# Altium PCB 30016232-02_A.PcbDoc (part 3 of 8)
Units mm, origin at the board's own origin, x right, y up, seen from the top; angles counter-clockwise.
Board outline 210 x 130 mm, 8 copper layers (1-TOP, 2-GND, 3-INTOP, 4-PWR, 5-PWR, 6-INBOT, 7-GND, 8-BOTTOM), stack 1.646 mm thick; 754 components, 649 nets, 2976 pads, 2161 vias.
Unrouted connection lines stored in the file: 22.
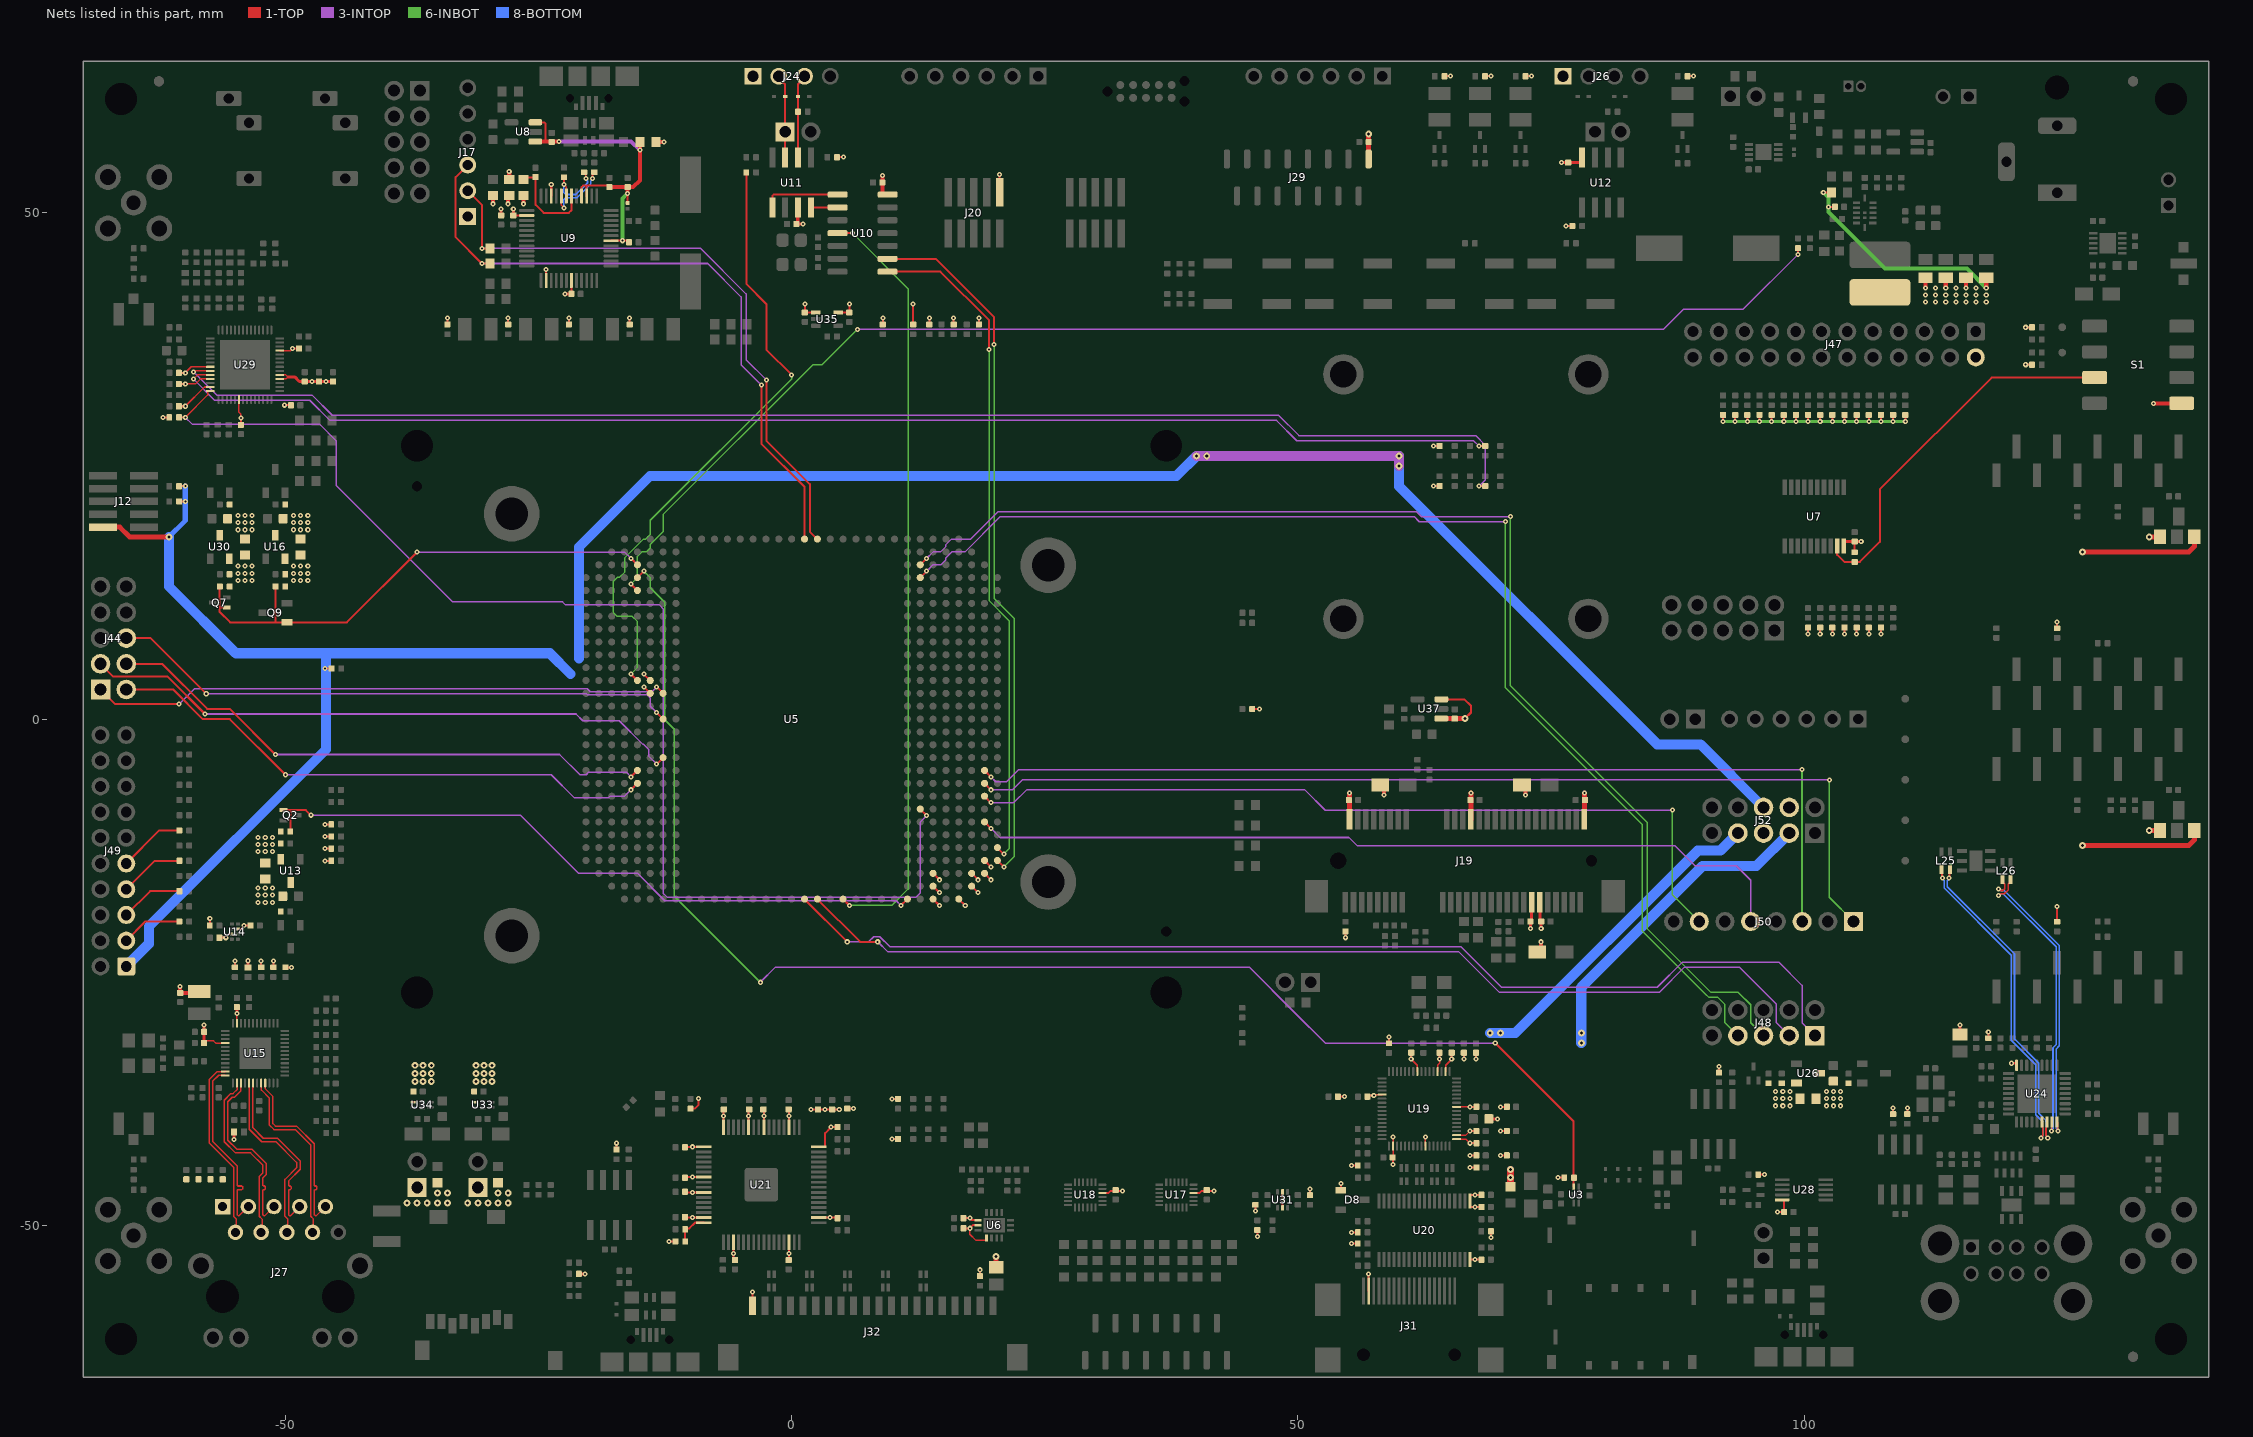
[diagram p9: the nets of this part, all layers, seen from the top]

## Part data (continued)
J3 J6 J7 J8 J9 J23 J25 J36: library part 1001128, "CONN HEADER 2POS .100\" SGL GOLD", Manufacturer=Samtec, Manufacturer_Part_Number=TSW-102-07-G-S, Package_Type=TH
J4: library part 1001136, "CONN HEADER 2POS 1.25MM VERT TIN", Manufacturer=Molex, Manufacturer_Part_Number=53047-0210, Package_Type=TH
J10 J13 J15: library part 1000027, "RF Connectors U.FL RECEPTACLE SMT GLD M CONTACT", Manufacturer=Hirose, Package_Type=SMT
J11 J14 J51: library part 1002720, "CONN SMA JACK R/A 50 OHM L15.1MM PCB TH", Manufacturer="Bobbintron Electrical Corp", Package_Type=TH
J12 J20 J22: library part 1000034, "CONN HEADER 10POS DUAL .05\" SMD", Manufacturer=Samtec, Package_Type=SMT
J16 J34 J35: library part 1001117, "CONN RECEPT MICRO-USB TYPE AB R/A", Manufacturer=KYCON, Package_Type=SMT
J17 J28 J43 J46: library part 1002721, "CONN HEADER VERT 6POS 2.54MM", Manufacturer=Molex, Package_Type=TH
J18: library part 1001118, "CONN TRANSFLSH R/A PUSH-PUSH SMD", Manufacturer=Molex, Package_Type=SMT
J19: library part 1001130, "SMCONN,MINI PCI EXP, 6.8MM HT", Manufacturer=Foxconn, Manufacturer_Part_Number=AS0B226-S68Q-7H, Package_Type=SMT
J21: library part 1001120, "MEMORY CARD 6POS PUSH/PULL SMD", Manufacturer=Molex, Package_Type=SMT
J24 J26: library part 1002743, "CONN HEADER VERT 4POS 2.54MM", Manufacturer=Semtech, Manufacturer_Part_Number=TSW-104-14-G-S, Package_Type=TH
J27: library part 1002612, "CONN MAGJACK 1PORT 1000 BASE-T IND", Manufacturer=XMultiple, Manufacturer_Part_Number=XMG-J1B2211NPA-1-DIG, Package_Type=TH
J29 J30: library part 1001866, "CONN FFC FPC VERT 15POS 1MM SMD", Manufacturer=FCI, Package_Type=SMT
J31: library part 1001123, "HDMI RECEPTACLE, SMT", Manufacturer=KYCON, Package_Type=SMT
J32: library part 1001132, "CONN HEADER 20POS 1.25MM R/A SMD", Manufacturer=Hirose, Manufacturer_Part_Number=DF14A-20P-1.25H, Package_Type=SMT
J33: library part 1001121, "USB Stacked Dual A type", Manufacturer=KYCON, Package_Type=TH
J37 J38: library part 1002596, "CONN JACK STEREO 3.5MM R/A", Manufacturer="CUI Inc.", Manufacturer_Part_Number=SJ1-3533NG, Package_Type=TH
J39 J40 J41 J42: library part 1001495, "CONN RCPT 2MM 10POS SMD", Manufacturer=Samtec, Package_Type=SMT
J44 J45 J48 J52 J53: library part 1001335, "CONN HEADER 10POS DL VERT T/H", Manufacturer=Molex, Manufacturer_Part_Number=87914-1016, Package_Type=TH
J47: library part 1002752, "CONN HEADER VERT 24POS 2.54MM", Manufacturer=Samtec, Package_Type=TH
J49: library part 1002751, "CONN HEADER VERT 20POS 2.54MM", Manufacturer=Samtec, Package_Type=TH
J50: library part 1000191, "CONN HEADER 8POS .100\" SNGL", Manufacturer=Samtec, Manufacturer_Part_Number=TSW-108-07-G-S, Package_Type=TH
L1: library part 1002747, "FIXED IND 4.7UH 4.5A 27.6 MOHM", Manufacturer=Murata, Manufacturer_Part_Number=1255AY-4R7M{}P3, Package_Type=SMT
L2 L4 L17 L18 L19 L22 L23 L24 L27 L29 L30 L31 L38 L39 L40 L41: library part 1001174, "FERRITE BEAD 220 OHM 2.0A 0805", Manufacturer="Wurth Electronics Inc", Manufacturer_Part_Number=742792022, Package_Type=0805
L3 L20 L21 L25 L26 L28: library part 1001173, "CHOKE COM MODE 120 OHM .37A", Manufacturer="Wurth Electronics Inc", Package_Type=SMT
L5: library part 1002610, "FIXED IND 4.7UH 1.1A 110 MOHM", Manufacturer=Samsung, Manufacturer_Part_Number=CIG22L4R7MNE, Package_Type=2520, Tolerance=20%
L6 L7: library part 1001175, "FERRITE BEAD 120 OHM .35A 0402", Manufacturer="Wurth Electronics Inc", Manufacturer_Part_Number=7427927112, Package_Type=0402
L8 L9 L10 L11 L12 L13 L14 L15 L16: library part 1001014, "CHOKE COIL COMMON MODE 150MA SMD", Manufacturer=Murata, Manufacturer_Part_Number=DLP11SN900HL2L, Package_Type=SMT
L32 L33 L34 L35 L36 L37: library part 1002041, "FERRITE BEAD 1.8 KOHM 0402 1LN", Manufacturer=Murata, Manufacturer_Part_Number=BLM15HD182SN1D, Package_Type=0402
Q1 Q2 Q4 Q6 Q7 Q11 Q12 Q13: library part 1000715, "MOSFET N-CH 60V 115MA SOT-523F", Manufacturer="Fairchild Semiconductor", Package_Type=SOT523F
Q3 Q5 Q8 Q9 Q10: library part 1000306, "MOSFET N-CH 30V 500MA SOT-23", Manufacturer="On Semiconductor", Package_Type=SOT23
R1 R231 R251 R254 R255 R256: library part 1001155, "RES 47.0K OHM 1/16W 1% 0402 SMD", Manufacturer="Vishay Dale", Manufacturer_Part_Number=CRCW040247K0FKED, Package_Type=0402, Tolerance=1%
R2 R4 R5 R6 R8 R22 R36 R37 R38 R39 R40 R41 R43 R44 R45 R47 R48 R49 R50 R51 R52 R54 R55 R56 R57 R58 R59 R60 R61 R62 R78 R125 R126 R127 R128 R129 R130 R131 R155 R156 R165 R167 R179 R224 R229 R232 R269 R270 R271 R272 R274 R275 R276 R277 R286 R287 R288 R289 R290 R293 R296 R297 R298 R299 R300 R301 R302 R303 R304 R305 R306 R308 R309 R310 R311 R313 R322 R323 R326 R328 R330 R331 R332 R333 R334 R335 R336 R340 R342 R343 R344 R345 R346 R347 R352 R353 R354 R359 R360: library part 1000076, "RES 0.0 OHM 1/10W 0402 SMD", Manufacturer="Panasonic - ECG", Manufacturer_Part_Number=ERJ-2GE0R00X, Package_Type=0402, Power=10
R3 R9 R11 R20 R21 R25 R80 R82 R84 R101 R102 R103 R104 R105 R106 R107 R108 R109 R110 R111 R112 R113 R114 R115 R116 R158 R174 R260 R281 R285 R317 R318 R319 R320 R321 R341 R348 R357: library part 1000480, "RES 100K OHM 1/10W 1% 0402 SMD", Manufacturer="Panasonic - ECG", Manufacturer_Part_Number=ERJ-2RKF1003X, Package_Type=0402, Power=100, Tolerance=1%
R7 R42 R46 R53 R117 R157 R159 R160 R164 R171 R173 R177 R181 R183 R184 R186 R187 R188 R189 R190 R191 R192 R193 R195 R196 R197 R198 R199 R200 R201 R202 R225 R243 R244 R247 R248 R250 R252 R258 R261 R262 R268 R279 R283 R307 R312 R337 R338 R350 R351: library part 1000537, "RES 10.0K OHM 1/10W 1% 0402 SMD", Manufacturer="Panasonic - ECG", Manufacturer_Part_Number=ERJ-2RKF1002X, Package_Type=0402, Power=100, Tolerance=1%
R10: library part 1001154, "RES 220 OHM 1/16W 1% 0402 SMD", Manufacturer=Yageo, Manufacturer_Part_Number=RC0402FR-07220RL, Package_Type=0402, Tolerance=1%
R12 R13 R18 R19 R28 R29 R30 R31 R32 R33 R34 R35 R63 R64 R65 R66 R67 R68 R132 R133 R134 R135 R136 R141 R142 R146 R147 R151 R152 R153 R154 R170 R203 R204 R205 R206 R207 R208 R209 R210 R211 R212 R213 R214 R215 R216 R217 R218 R219 R220 R221 R222 R223 R235 R236 R237 R238 R239 R240 R241 R257 R263 R265 R266 R267 R278 R282 R349 R355 R356: library part 1000208, "RES 0.0 OHM 1/10W 0603", Manufacturer="Panasonic - ECG", Manufacturer_Part_Number=ERJ-3GEY0R00V, Package_Type=0603, Voltage=75V
R14 R27 R137 R175 R253: library part 1001200, "RES 12.0K OHM 1/10W 1% 0603 SMD", Manufacturer=Yageo, Manufacturer_Part_Number=RC0603FR-0712KL, Package_Type=0603, Power=100, Tolerance=1
R15 R273 R291 R292 R294 R295 R327 R329: library part 1001156, "RES 2.20K OHM 1/16W 1% 0402 SMD", Manufacturer=Yageo, Manufacturer_Part_Number=RC0402FR-072K2L, Package_Type=0402, Tolerance=1%
R16: library part 1000711, "RES 10.0 OHM 1/10W 1% 0402 SMD", Manufacturer="Panasonic - ECG", Manufacturer_Part_Number=ERJ-2RKF10R0X, Package_Type=0402, Power=100, Tolerance=1%
R17 R140 R358: library part 1000142, "RES 20K OHM 1/10W 5% 0603 SMD", Manufacturer="Panasonic - ECG", Manufacturer_Part_Number=ERJ-3GEYJ203V, Package_Type=0603, Power=100, Tolerance=5
R23 R26: library part 1000701, "RES 470K OHM 1/10W 1% 0402 SMD", Manufacturer="Panasonic - ECG", Manufacturer_Part_Number=ERJ-2RKF4703X, Package_Type=0402, Power=100, Tolerance=1%
R24: library part 1001518, "RES 53.6K OHM 1/10W 1% 0603 SMD", Manufacturer="Panasonic - ECG", Manufacturer_Part_Number=ERJ-3EKF5362V, Package_Type=0603
R69 R70 R71 R72 R138 R139 R161 R324 R325: library part 1000601, "RES 22.0 OHM 1/10W 1% 0402 SMD", Manufacturer="Panasonic - ECG", Manufacturer_Part_Number=ERJ-2RKF22R0X, Package_Type=0402, Power=100, Tolerance=1%
R73 R74 R75 R76 R162 R163: library part 1000466, "RES 49.9 OHM 1/10W 1% 0402 SMD", Manufacturer="Panasonic - ECG", Manufacturer_Part_Number=ERJ-2RKF49R9X, Package_Type=0402, Power=100, Tolerance=1%
R77 R79 R81 R83 R85 R86 R87 R88 R89 R90 R91 R92 R93 R94 R95 R96 R97 R98 R99 R100 R118 R119 R120 R121 R122 R123 R124 R185 R233 R234 R242 R245 R246: library part 1000038, "RES 4.7K OHM 1/10W 5% 0402 SMD", Manufacturer="Panasonic - ECG", Manufacturer_Part_Number=ERJ-2GEJ472X, Package_Type=0402, Power=100, Tolerance=5
R143 R144 R148 R150 R166 R169 R172 R176 R182 R259 R280 R284 R314 R315 R316: library part 1001158, "RES 120 OHM 1/16W 1% 0402 SMD", Manufacturer=Yageo, Manufacturer_Part_Number=RC0402FR-07120RL, Package_Type=0402, Tolerance=1%
R145: library part 1001772, "SMRES, 1.5K OHM 0.063W 0402 1%", Manufacturer="Vishay Dale", Manufacturer_Part_Number=CRCW04021K50FKED, Package_Type=0402, Power=63, Tolerance=1%
R149: library part 1001000, "RES 470 OHM 1/20W 1% 0201 SMD", Manufacturer=KOA, Manufacturer_Alt_1="Panasonic - ECG", Manufacturer_Alt_1_Part_Number=ERJ-1GNF4700C, Manufacturer_Alt_2="Vishay Dale", Manufacturer_Alt_2_Part_Number=CRCW0201470RFKED, Manufacturer_Part_Number=RK73H1HTTC4700F, Package_Type=0201, Power=50, Tolerance=1
R168 R178 R264: library part 1000079, "RES 1.00K OHM 1/10W 1% 0402 SMD", Manufacturer="Panasonic - ECG", Manufacturer_Part_Number=ERJ-2RKF1001X, Package_Type=0402, Power=10
R180: library part 1000229, "RES 0.0 OHM 1/2W 1210 SMD", Manufacturer="Vishay Dale", Manufacturer_Part_Number=CRCW12100000Z0EA, Package_Type=1210
R194: library part 1000469, "RES 2.37K OHM 1/10W 1% 0402 SMD", Manufacturer="Panasonic - ECG", Manufacturer_Part_Number=ERJ-2RKF2371X, Package_Type=0402, Power=100, Tolerance=1%
R226: library part 1001153, "RES 27.0K OHM 1/16W 1% 0402 SMD", Manufacturer=Yageo, Manufacturer_Part_Number=RC0402FR-0727KL, Package_Type=0402, Tolerance=1%
R227 R249: library part 1000971, "RES 1.00M OHM 1/16W 1% 0402 SMD", Manufacturer=Yageo, Manufacturer_Part_Number=RC0402FR-071ML, Package_Type=0402, Power=63, Tolerance=1
R228: library part 1002748, "RES 5.97K OHM 0.1% 1/10W 0402", Manufacturer="Vishay Dale", Manufacturer_Part_Number=TNPW04025K97BEED, Package_Type=0402
R230: library part 1000174, "RES 15.0K OHM 1/10W 1% 0402 SMD", Manufacturer="Panasonic - ECG", Manufacturer_Part_Number=ERJ-2RKF1502X, Package_Type=0402, Power=10, Tolerance=1%
R339: library part 1000980, "RES 2.2M OHM 1/20W 5% 0201 SMD", Manufacturer=Rohm, Manufacturer_Alt_1="Panasonic - ECG", Manufacturer_Alt_1_Part_Number=ERJ-1GEJ225C, Manufacturer_Part_Number=MCR006YZPJ225, Package_Type=0201, Power=50, Tolerance=5
S1: library part 1002122, "SWITCH SLIDE DIP SPST 100MA 20V", Manufacturer=CTS, Package_Type=SOIC
SW1 SW2 SW3 SW4: library part 1001124, "SWITCH TACTILE SPST-NO 0.05A 32V", Manufacturer=ITT, Package_Type=SMT
SWD: library part CAD0066, "CBL PLUG-OF-NAILS 10-PIN", Package_Type=SMT
TP1 TP2 TP3 TP4 TP5 TP6 TP7: library part CAD0011, "TEST POINT 30MIL PAD SMT", Package_Type=TP
U1: library part 1002744, "IC ELECTRONIC FUSE 10VFDFPN", Manufacturer=STMicroelectronics, Package_Type=SON
U2 U8 U37: library part 1001979, "IC REG LDO ADJ 0.15A SOT25", Manufacturer="Diodes, Inc.", Manufacturer_Part_Number=AP2202K-ADJTRG1, Package_Type=SOT23-5
U3 U33 U34: library part 1001857, "IC SW W/CTRL SLEW RATE 4TDFN", Manufacturer="Vishay Siliconix", Manufacturer_Part_Number=SIP32401ADNP-T1GE4, Package_Type=SON
U4: library part 1001907, "IC REG BUCK ADJ 3A SYNC", Manufacturer="Linear Technology", Manufacturer_Part_Number=MP2316GD, Package_Type=QFN
U5: library part 1002739, "ConnectCore for i.MX8M Nano module - LGA", Manufacturer=DIGI, Manufacturer_Part_Number=50002014-01
U6: library part 1002449, "SMIC PCIE CLOCK GEN 100MHZ 14QFN", Manufacturer="Abracon Corporation", Package_Type=QFN
U7: library part 1001368, "IC SWITCH BUS 8BIT FET 20-TSSOP", Manufacturer="Texas Instruments", Package_Type=TSSOP
U9: library part 1002724, "IC USB FS DUAL UART/FIFO 48-LQFP", Manufacturer="FTDI Chip", Package_Type=QFP
U10: library part 1002729, "IC CANBUS CONTROLLER SPI 14SOIC", Manufacturer=Microchip, Manufacturer_Part_Number=MCP2517FD-H/SL, Package_Type=SOIC
U11: library part 1002681, "IC CAN TRANSEIVER HS 8SOIC", Manufacturer="Texas Instruments", Package_Type=SOIC
U12: library part 1001420, "IC TRANSCEIVER RS485 8-SOIC", Manufacturer="Linear Technology", Package_Type=SOIC
U13 U16 U26 U30: library part 1001163, "MOSFET P-CH 20V 3.7A SOT23-3", Manufacturer="Vishay Siliconix", Package_Type=SMT
U14: library part 1002597, "IC TRANSLATING TXRX 8XSON", Manufacturer="NXP Semiconductors", Manufacturer_Part_Number=NTS0102GT,115, Package_Type=PSON
U15: library part 1002583, "IC TRANSCEIVER ETHERNET 48-QFN", Manufacturer="Qualcomm Atheros, Inc.", Package_Type=QFN
U17 U18: library part 1002697, "IC SWITCH TPDT DIFF XQFN24", Manufacturer="NXP Semiconductors", Manufacturer_Part_Number=NX3DV642GU, Package_Type=QFN
U19: library part 1002722, "MIPI DSI BRIDGE TO LVDS/HDMI SINGLE CHANNEL", Manufacturer="Lontium Semiconductor", Package_Type=QFN
U20: library part 1001125, "IC HDMI XMITTER PORT P/I 38TSSOP", Manufacturer="On Semiconductor", Package_Type=SOP
U21: library part 1002718, "IC BRIDGE DSI TO LVDS 64HTQFP", Manufacturer="Texas Instruments", Package_Type=QFP
U22 U25: library part 1001265, "TVS DIODE 5.5VWM 6SON", Manufacturer="Texas Instruments", Package_Type=SMT
U23 U27 U36: library part 1001143, "IC SW DISTRIBUTION 2CHAN 8SOIC", Manufacturer=Micrel, Manufacturer_Part_Number=MIC2026-1YM, Package_Type=SOIC
U24: library part 1001114, "4-PORT USB 2.0 HUB CTRLR 36VQFN", Manufacturer=SMSC, Package_Type=QFN
U28: library part 1002730, "IC USB SWITCH DUAL 2X1 10MSOP", Manufacturer="On Semiconductor", Package_Type=SOP
U29: library part 1002001, "IC CODEC AUDIO FLEXSOUND 56TQFN", Manufacturer=Maxim, Manufacturer_Part_Number=MAX98089ETN+T, Package_Type=QFN
U31: library part 1001009, "MOSFET DL N-CH 60V 410MA SOT-563", Manufacturer="Diodes, Inc.", Package_Type=SOT523F
U32: library part 1000217, "IC OPAMP DUAL 1.6V 9KHZ 8TDFN", Manufacturer=Microchip, Package_Type=DFN
U35: library part 1000759, "TRANSLATOR 1BIT UNIDIRECT SC70-", Manufacturer="Fairchild Semiconductor", Package_Type=SC70
X1: library part 1002725, "Crystals 6MHz lo-profile", Manufacturer="Vishay Semiconductors", Manufacturer_Part_Number=XT9M20HRR6M, Package_Type=SMT
X2: library part 1002203, "CRYSTAL 40.0000MHz 9pF -40°C - 85°C DFN LCC", Manufacturer=Raltron, Package_Type=OSCCC
X3 X4: library part 1001497, "SMCRY,25MHZ 50PPM 20PF RH100 EXT", Manufacturer=Raltron, Package_Type=SMT
X5: library part 1001134, "CRYSTAL 24MHZ 18PF SMD", Manufacturer=Aker, Manufacturer_Part_Number=C3E-24.000-18-3030-X-R, Package_Type=SMT

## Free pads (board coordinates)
  round 5.5 / inner round 0 / far side round 5.5 hole 3.2: 0(-27.65,-21.4) 0(-27.65,20.275) 0(25.35,-16.1) 0(25.35,15.2)
  round 4 / inner round 0 / far side round 5.5 hole 2.6: 0(54.5,34.05) 0(78.7,34.05) C(54.5,9.9) C(78.7,9.9)

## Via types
v1: diameter 0.5, hole 0.2, 1-TOP to 8-BOTTOM, 1742 vias
v2: diameter 0.5/0.5/0.5/0.5 (per signal layer), hole 0.2, 1-TOP to 8-BOTTOM, 237 vias
v3: diameter 0.68, hole 0.3, 1-TOP to 8-BOTTOM, 182 vias

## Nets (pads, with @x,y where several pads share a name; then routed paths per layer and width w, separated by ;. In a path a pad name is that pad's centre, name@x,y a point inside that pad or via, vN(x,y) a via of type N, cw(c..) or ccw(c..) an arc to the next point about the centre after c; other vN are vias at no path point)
1V8: C190.2 R37.1 R77.2 R79.2 R81.1 R83.1 R323.1 R345.1 R347.1 U5.AH1 U5.AH2 U5.AH3 U34.3 | length 7.7
  1-TOP w0.2: v1(-46.12,-14) R347.1@-45.48,-14 ; v1(-46.1,-12.8) R345.1@-45.48,-12.8 ; v1(-46.1,-11.6) R37.1@-45.48,-11.6 ; R323.1@9,38.98 v1(9,39.6) ; U5.AH1@13.97,-17.78 v1(14.605,-18.415) ; U5.AH2@13.97,-16.51 v1(14.605,-17.145) ; U5.AH3@13.97,-15.24 v1(14.605,-15.875) ; R81.1@15.99,39 v1(15.99,39.62) ; R83.1@18.5,38.98 v1(18.5,39.62) ; v1(121.9,35) R79.2@122.52,35 ; v1(121.9,38.7) R77.2@122.52,38.7
  other v3: -37.2,-35.8 -36.4,-35.8 -35.6,-35.8 -37.2,-35 -36.4,-35 -35.6,-35 -37.2,-34.2 -36.4,-34.2 -35.6,-34.2
1V8_CODEC: C162.2 C164.2 C165.1 C166.1 C167.1 R282.2 R284.1 U16.D U29.25 U29.50 U29.53 | length 9.3
  1-TOP w0.15: v1(-59.9,33.1) -58.9,33.1 -58.4,33.6 U29.53@-57.43,33.6 ; v1(-59.9,34.2) -59.3,34.8 U29.50@-57.43,34.8 ; U29.25@-50.57,36.4 -49.5,36.4 v1(-49.3,36.6)
  1-TOP w0.2: C166.1@-60.54,33.1 v1(-59.9,33.1) ; C165.1@-60.54,34.2 v1(-59.9,34.2) ; v1(-50.1,31) C164.2@-49.46,31 ; v1(-49.3,36.6) C167.1@-48.66,36.6
  other v1: -49.2,18.7 -48.5,18.7 -47.8,18.7 -49.2,19.4 -48.5,19.4 -47.8,19.4 -49.2,20.1 -48.5,20.1 -47.8,20.1
1V8_SOM_EXT: C60.2 C87.2 C88.2 C89.2 C90.2 C91.2 C94.2 C95.2 C97.2 C98.2 C99.2 C100.2 C102.2 C103.2 C104.2 C105.2 C106.2 C107.2 C108.2 C109.2 C112.2 C113.2 C114.2 C115.2 C116.2 C117.2 C118.2 C119.2 C120.2 C121.2 C122.2 C123.2 C197.2 J8.1 J20.1 J52.7 R32.2 R164.1 R173.1 R183.2 R224.2 R225.1 R231.1 R245.2 R282.1 R283.1 R285.1 R294.2 R295.2 R327.2 R329.2 U14.3 U16.S U19.5 U19.18 U19.26 U19.33 U19.34 U19.41 U19.50 U19.52 U19.57 U21.3 U21.14 U21.18 U21.32 U21.35 U21.40 U21.43 U21.48 U21.49 U21.55 U21.58 U21.63 U31.2 U31.5 U35.5 | length 96.3
  1-TOP w0.15: v1@57.5,-37.1 U19.5@58.32,-37.1 ; C89.2@59.4,-43.3 U19.18@59.4,-42.18 v1(59.4,-41.3) ; v1(61.2,-33.6) 61.8,-34.2 U19.57@61.8,-34.82 ; U19.26@62.6,-42.18 v1(62.6,-41.3) ; U19.52@63.8,-34.82 63.8,-34.2 64,-34 v1(64,-33.6) ; U19.50@64.6,-34.82 64.6,-34.2 v1(65.2,-33.6) ; U19.33@65.68,-41.5 66.6,-41.5 v1(67,-41.9) ; U19.34@65.68,-41.1 66.6,-41.1 v1(67,-40.7) ; U19.41@65.68,-38.3 v1(67,-38.3)
  1-TOP w0.2: R173.1@-57.48,-20.4 v1(-57.48,-19.7) ; U14.3@-54.7,-20.75 -54.699,-20.749 -54.399,-20.749 -54.05,-20.4 C60.2@-53.46,-20.4 ; R183.2@-50,-24.52 v1(-49.4,-24.52) ; v1(-12.1,-51.6) R245.2@-11.48,-51.6 ; C120.2@-10.44,-49.25 v1(-9.8,-49.25) U21.63@-8.68,-49.25 ; C114.2@-10.44,-46.75 v1(-9.8,-46.75) U21.58@-8.68,-46.75 ; C112.2@-10.44,-45.25 v1(-9.8,-45.25) U21.55@-8.68,-45.25 ; C123.2@-10.44,-42.25 v1(-9.8,-42.25) U21.49@-8.68,-42.25 ; U21.48@-6.75,-40.32 v1(-6.75,-39.2) C113.2@-6.75,-38.46 ; C122.2@-5.75,-53.44 v1(-5.75,-52.8) U21.3@-5.75,-51.68 ; U21.43@-4.25,-40.32 v1(-4.25,-39.2) C119.2@-4.25,-38.46 ; U21.40@-2.75,-40.32 v1(-2.75,-39.2) C116.2@-2.75,-38.46 ; C118.2@-0.25,-53.44 v1(-0.25,-52.8) U21.14@-0.25,-51.68 ; U21.35@-0.25,-40.32 v1(-0.25,-39.2) C115.2@-0.25,-38.46 ; v1(1.9,-38.56) C108.2@2.6,-38.56 v1(3.3,-38.56) C109.2@4,-38.56 v1(4.7,-38.56) ; U21.18@2.68,-49.25 v1(3.8,-49.25) C117.2@4.54,-49.25 ; U21.32@3.3,-42.2 3.3,-40.9 v1(3.9,-40.3) C121.2@4.54,-40.3 ; U35.5@4.59,40.15 C197.2@5.69,40.15 ; C197.2@5.7,40.16 v1(5.7,41) ; v1(9.9,-41.48) R295.2@10.5,-41.48 ; v1(9.9,-37.52) R294.2@10.5,-37.52 ; R164.1@12,38.98 v1(12,41) ; J20.1@20.54,52.032 v1(20.54,53.8) ; v1(45.8,-48.6) R329.2@45.8,-47.98 ; U31.5@48.5,-48.28 v1(48.5,-47.5) U31.2@48.5,-46.72 ; R327.2@51.2,-47.02 v1(51.2,-46.4) ; C94.2@53.96,-37.3 v1(54.6,-37.3) ; v1(55.3,-44.1) R231.1@55.92,-44.1 ; C95.2@56.86,-37.2 v1(57.5,-37.2) ; R225.1@59,-32.02 v1(59,-31.4) ; v1(59.4,-44) C89.2@59.4,-43.36 ; v1(61.2,-33.6) C91.2@61.2,-32.96 ; v1(64,-33.6) C107.2@64,-32.96 ; v1(65.2,-33.6) C105.2@65.2,-32.96 ; v1(66.4,-33.6) C106.2@66.4,-32.96 ; v1(67,-44.3) C88.2@67.64,-44.3 ; v1(67,-43.1) C98.2@67.64,-43.1 ; v1(67,-41.9) C90.2@67.64,-41.9 ; v1(67,-40.7) C100.2@67.64,-40.7 ; v1(67,-38.3) C103.2@67.64,-38.3 ; v1(67.6,-33.6) C104.2@67.6,-32.96 ; v1(69.08,-51.2) R224.2@69.08,-50.6 ; v1(70,-43.1) C97.2@70.64,-43.1 ; v1(70,-40.7) C99.2@70.64,-40.7 ; v1(70,-38.3) C102.2@70.64,-38.3
  1-TOP w0.3: C87.2@68.87,-39.5 v1(69.7,-39.5)
  8-BOTTOM w1: v3(69,-31) v3(70,-31) 71.5,-31 89.5,-13 91.73,-13 J52.7@93.46,-11.27
  other v1: -54.1,-20.4 -49.2,13.7 -48.5,13.7 -47.8,13.7 -49.2,14.4 -48.5,14.4 -47.8,14.4 -49.2,15.1 -48.5,15.1 -47.8,15.1
  other v3: -38,-47.8 -37,-47.8 -36,-47.8 -35,-47.8 -34,-47.8 -35,-46.8 -34,-46.8
3V3: C28.2 C186.2 R36.1 R38.1 R39.1 R85.1 R86.1 R87.1 R88.1 R89.1 R90.1 R91.1 R92.1 R93.1 R94.1 R95.1 R96.1 R97.1 R98.1 R99.1 R100.1 R117.1 R118.1 R119.1 R120.1 R121.1 R122.1 R123.1 R124.1 R344.1 R346.1 U5.AK1 U5.AL2 U5.AL3 U5.AM3 U5.AM4 U7.20 U33.3 | length 45.3
  1-TOP w0.2: v1(-46.1,-10.4) R38.1@-45.48,-10.4 ; R344.1@-10,-38.48 -9.58,-38.48 -9.2,-38.1 v1(-9.2,-37.5) ; R36.1@5.5,-38.48 v1(6.1,-38.48) ; R39.1@13.6,38.96 v1(13.6,39.6) ; U5.AK1@16.51,-17.78 v1(17.145,-18.415) ; U5.AL2@17.78,-16.51 v1(18.415,-17.145) ; U5.AL3@17.78,-15.24 v1(18.415,-15.875) ; U5.AM3@19.05,-15.24 v1(19.685,-15.875) ; U5.AM4@19.05,-13.97 v1(19.685,-14.605) ; R346.1@45.48,1 v1(46.22,1) ; v1(92,29.376) R92.1@92,30.04 ; v1(93.2,29.376) R100.1@93.2,30.04 ; v1(94.4,29.376) R91.1@94.4,30.04 ; v1(95.6,29.376) R99.1@95.6,30.04 ; v1(96.8,29.376) R90.1@96.8,30.04 ; v1(98,29.376) R98.1@98,30.04 ; v1(99.2,29.376) R89.1@99.2,30.04 ; v1@100.4,8.3 v1(100.4,8.4) R124.1@100.4,9.04 ; v1(100.4,29.376) R97.1@100.4,30.04 ; v1@101.6,8.3 v1(101.6,8.4) R120.1@101.6,9.04 ; v1(101.6,29.376) R88.1@101.6,30.04 ; v1@102.8,8.3 v1(102.8,8.4) R123.1@102.8,9.04 ; v1(102.8,29.376) R96.1@102.8,30.04 ; v1@104,8.3 v1(104,8.4) R122.1@104,9.04 ; v1(104,29.376) R87.1@104,30.04 ; R117.1@105,16.48 C28.2@105,17.54 ; v1@105.2,8.3 v1(105.2,8.4) R119.1@105.2,9.04 ; v1(105.2,29.376) R95.1@105.2,30.04 ; v1@106.4,8.3 v1(106.4,8.4) R121.1@106.4,9.04 ; v1(106.4,29.376) R86.1@106.4,30.04 ; v1@107.6,8.3 v1(107.6,8.4) R118.1@107.6,9.04 ; v1(107.6,29.376) R94.1@107.6,30.04 ; v1(108.8,29.376) R85.1@108.8,30.04 ; v1(110,29.376) R93.1@110,30.04
  1-TOP w0.3: U7.20@103.9,17.54 C28.2@105,17.54 v1(105.65,17.54)
  6-INBOT w0.3: v1(92,29.376) v1(99.2,29.376) v1(100.4,29.376) v1(101.6,29.376) v1(102.8,29.376) v1(104,29.376) v1(105.2,29.376) v1(106.4,29.376) v1(107.6,29.376) v1(108.8,29.376) v1(110,29.376)
  other v3: -31.2,-35.8 -30.4,-35.8 -29.6,-35.8 -31.2,-35 -30.4,-35 -29.6,-35 -31.2,-34.2 -30.4,-34.2 -29.6,-34.2
3V3_BOARD: C15.2 C16.2 C17.2 C18.2 C21.2 C26.2 C27.2 C47.1 C48.1 C49.1 C50.2 C51.2 C52.2 C53.2 C54.2 C199.2 J19.2 J19.24 J19.39 J19.41 J19.52 J52.5 L1.2 L39.1 L41.1 R24.2 R160.2 R306.2 R311.2 U6.1 U6.12 U6.13 U37.1 U37.3 | length 82
  1-TOP w0.15: v1(17.6,-50.3) 17.6,-50.9 18.2,-51.5 U6.1@19.2,-51.5
  1-TOP w0.2: C27.2@16.96,-50.3 v1(17.6,-50.3) 17.9,-50 U6.13@18.4,-50 ; C26.2@16.96,-49.3 v1(17.6,-49.3) 17.8,-49.5 U6.12@18.4,-49.5 ; v1(54.7,-21.6) R160.2@54.7,-20.98 ; U37.3@64.18,1.95 66.45,1.95 67.1,1.3 67.1,0.65 v3(66.5,0.05) ; v1(101.9,52) R24.2@102.7,52 ; v1(102.4,50.6) C21.2@103.04,50.6 ; R306.2@125,-20.02 v1(125,-18.5) ; R311.2@125,8.98 v1(125,9.6)
  1-TOP w0.3: v1(72.96,-20.675) C53.2@72.96,-20 ; C53.2@73.1,-20 J19.39@73.1,-18.1 ; C54.2@73.9,-20 J19.41@73.9,-18.1 ; v1(74.04,-20.675) C54.2@74.04,-20
  1-TOP w0.4: C47.1@58.15,-6.5 58.5,-6.85 v1(58.5,-7.5) ; C48.1@72.15,-6.5 72.5,-6.85 v1(72.5,-7.5) ; C49.1@73.65,-23 74,-22.65 v1(74,-22) ; v1@112,42.7 C18.2@112,43.6 ; v1@114,42.7 C17.2@114,43.6 ; v1@116,42.7 C16.2@116,43.6 ; v1@118,42.7 C15.2@118,43.6
  1-TOP w0.5: J19.2@55.1,-9.9 v1(55.1,-7.3) ; U37.1@64.18,0.05 v3(66.5,0.05) ; J19.24@67.1,-9.9 v1(67.1,-7.3) ; J19.52@78.3,-9.9 v1(78.3,-7.3) ; v3(127.5,-12.5) 138,-12.5 138.55,-11.95 L39.1@138.55,-11 ; v3(127.5,16.5) 138,16.5 138.55,17.05 L41.1@138.55,18
  6-INBOT w0.4: v1(101.9,52) 102.4,51.5 v1(102.4,50.6) 102.4,50.1 108,44.5 116.1,44.5 v1(118,42.6)
  other v1: 112,41.2 113,41.2 114,41.2 115,41.2 116,41.2 117,41.2 118,41.2 112,41.9 113,41.9 114,41.9 115,41.9 116,41.9 117,41.9 118,41.9 112,42.6 113,42.6 114,42.6 115,42.6 116,42.6 117,42.6
3V3_BOARD_EN: R22.1 U5.E25 | length 132.7
  1-TOP w0.2: v1(-15.875,13.335) U5.E25@-15.24,12.7 ; v1(99.4,45.9) R22.1@99.4,46.52
  3-INTOP w0.15: v1(6.5,38.5) 86.128,38.5 88.128,40.5 94,40.5 v1(99.4,45.9)
  6-INBOT w0.15: v1(-15.875,13.335) -15.24,13.97 -15.24,16.06 -14.79,16.51 -14.36,16.51 -13.97,16.9 -13.97,17.23 -12.7,18.5 -12.7,20.2 2.1,35 3,35 v1(6.5,38.5)
3V3_CODEC: C158.2 C159.2 C161.2 C171.2 C172.1 C173.1 R278.2 R280.1 U29.6 U29.18 U29.19 U29.55 U30.D | length 12.9
  1-TOP w0.15: v1(-59.9,30.9) -58,32.8 U29.55@-57.43,32.8 ; U29.6@-54.6,31.57 -54.6,30.3 -54.4,30.1 v1(-54.4,29.725) ; U29.18@-50.57,33.6 -49.963,33.6 -49.763,33.8 -49.963,34 U29.19@-50.57,34
  1-TOP w0.2: C161.2@-60.54,30.9 v1(-59.9,30.9) ; C159.2@-54.4,29.06 v1(-54.4,29.725)
  1-TOP w0.3: -49.763,33.8 -49.1,33.8 -48.64,33.34 C173.1@-48.1,33.34 v1(-47.4,33.34) C172.1@-46.7,33.34 C171.2@-45.3,33.34
  other v1: -54.7,18.7 -54,18.7 -53.3,18.7 -54.7,19.4 -54,19.4 -53.3,19.4 -54.7,20.1 -54,20.1 -53.3,20.1 -46,33.34
3V3_DBG: C40.2 C41.2 C42.2 J17.1 R133.2 R134.2 R136.2 R143.1 R144.1 R148.1 R150.1 U9.10 U9.14 U9.26 U9.31 | length 11.3
  1-TOP w0.2: R143.1@-34,38.98 v1(-34,39.6) ; R144.1@-28,38.98 v1(-28,39.6) ; C41.2@-27.3,49.75 U9.14@-26.17,49.75 ; U9.26@-24.25,43.33 v1(-24.25,44.4) ; U9.10@-23.75,51.67 v1(-23.75,52.8) ; R150.1@-22,38.98 v1(-22,39.6) ; C42.2@-21.75,42.2 U9.31@-21.75,43.33 ; R148.1@-16,38.98 v1(-16,39.6)
  1-TOP w0.3: C40.2@-28.7,49.76 v1(-28.7,50.4) ; C41.2@-27.5,49.76 v1(-27.5,50.4) ; v1(-22.4,42) C42.2@-21.76,42
  1-TOP w0.4: v1(-29.5,50.9) R136.2@-29.5,51.7 ; v1(-28,50.9) R133.2@-28,51.7 ; v1(-26.5,50.9) R134.2@-26.5,51.7
3V3_ETH: C61.2 C64.2 C66.2 C67.2 L6.1 R170.2 R172.1 R178.2 R181.1 U13.D U14.7 U15.4 | length 7.3
  1-TOP w0.15: C67.2@-58.04,-31.8 -57.1,-31.8 -56.9,-32 U15.4@-55.95,-32
  1-TOP w0.2: C61.2@-56.54,-21.6 -55.95,-21.6 -55.601,-21.251 U14.7@-55.3,-21.25 ; R178.2@-55,-24.52 v1(-55,-23.9) ; R181.1@-51.2,-24.52 v1(-51.2,-23.9)
  1-TOP w0.3: C67.2@-58.04,-32 -58.04,-31.8 C66.2@-58.04,-30.9 v1(-58.04,-30.2) ; v1(-55.08,-41.525) L6.1@-55.08,-40.8
  other v1: -55.9,-21.6 -52.7,-18.1 -52,-18.1 -51.3,-18.1 -52.7,-17.4 -52,-17.4 -51.3,-17.4 -52.7,-16.7 -52,-16.7 -51.3,-16.7
3V3_RF: J12.2 J49.1 J52.6 R42.2 R46.2 R53.2 U5.F17 U5.F18 | length 253.4
  1-TOP w0.2: R46.2@-60.52,21.5 v1(-59.9,21.5) ; R42.2@-60.52,23 v1(-59.9,23) ; v1(-46.08,5) R53.2@-45.46,5 ; v1(-14.605,3.175) U5.F17@-13.97,2.54 ; v1(-14.605,4.445) U5.F18@-13.97,3.81
  1-TOP w0.5: J12.2@-68.032,18.96 -66.36,18.96 -65.4,18 v3(-61.5,18)
  3-INTOP w1: v3(40,26) v3(60,26) v3(60,25)
  8-BOTTOM w0.5: v3(-61.5,18) -59.9,19.6 v1(-59.9,21.5) v1(-59.9,23)
  8-BOTTOM w1: J49.1@-65.73,-24.43 -63.5,-22.2 -63.5,-20.5 -46,-3 -46,6.5 ; v3(-61.5,18) -61.5,13.1 -54.9,6.5 -46,6.5 ; -21.845,4.445 -23.9,6.5 -33,6.5 -46,6.5 ; -21,6 -21,17 -14,24 38,24 v3(40,26) v3(41,26) ; v3(60,26) 60,23 85.5,-2.5 89.77,-2.5 J52.6@96,-8.73
3V3_SOM_EXT: C55.1 C59.2 C79.1 C80.1 C81.2 C144.1 C198.1 D8.A J7.1 J26.1 J29.1 J32.1 J47.2 J52.4 L38.1 L40.1 R10.2 R25.2 R31.2 R133.1 R156.2 R165.2 R170.1 R171.1 R174.1 R177.2 R244.1 R257.1 R258.1 R260.1 R261.2 R262.1 R268.1 R278.1 R279.1 R281.1 R291.2 R292.2 R314.2 R315.2 R316.2 R338.1 R351.2 S1.5 U10.14 U12.8 U13.S U17.10 U18.10 U26.S U28.10 U30.S U35.1 | length 32.3
  1-TOP w0.2: v1(-62.1,29.8) R268.1@-61.48,29.8 ; R261.2@-17.3,-42.52 v1(-17.3,-41.9) ; J32.1@-3.875,-57.95 v1(-3.875,-56.6) ; C198.1@1.3,40.05 v1(1.3,41) ; C198.1@1.3,40.15 U35.1@2.39,40.15 ; R165.2@4.48,55.5 v1(5.1,55.5) ; R244.1@18.6,-55.02 v1(18.6,-54.4) ; U18.10@30.695,-46.8 31.3,-46.8 31.5,-46.6 v1(32.7,-46.6) ; U17.10@39.695,-46.8 40.3,-46.8 40.5,-46.6 v1(41.7,-46.6) ; v1(46,-51.1) R338.1@46,-50.48 ; D8.A@54.25,-46.55 v1(54.25,-45.875) ; v1(63.4,23) R291.2@64,23 ; v1(63.4,26.96) R292.2@64,26.96 ; R316.2@64.48,63.5 v1(65.1,63.5) ; R314.2@68.48,63.5 v1(69.1,63.5) ; R315.2@72.48,63.5 v1(73.1,63.5) ; v1(75.7,-45.3) R25.2@76.32,-45.3 ; v1(76.5,48.7) R177.2@77.12,48.7 ; R10.2@88.48,63.5 v1(89.1,63.5) ; R351.2@91.6,-34.92 v1(91.6,-34.3) ; R262.1@95.48,-45 v1(96.1,-45) ; v1(97.4,-48.7) C144.1@98.04,-48.7 U28.10@98.04,-47.5
  1-TOP w0.3: R156.2@-21.02,-54.8 v1(-20.4,-54.8) ; v1(76.05,54.96) C59.2@76.7,54.96 U12.8@78.1,54.96
  1-TOP w0.4: R133.1@-27.9,53.3 v1(-27.9,54.1) ; U10.14@8.96,51.8 C55.1@8.96,53 v1(8.96,53.7) ; v1(134.5,31.19) S1.5@137.3,31.19
  1-TOP w0.5: J29.1@57,55.325 v3(57,57.8) ; v3(134.1,-11) L38.1@135.15,-11 ; v3(134.1,18) L40.1@135.15,18
  8-BOTTOM w0.8: J52.4@98.54,-8.73 J52.4@98.54,-8.54
  other v1: 97.2,-38.2 97.9,-38.2 98.6,-38.2 97.2,-37.5 97.9,-37.5 98.6,-37.5 97.2,-36.8 97.9,-36.8 98.6,-36.8 -52.7,-13.1 -52,-13.1 -51.3,-13.1 -52.7,-12.4 -52,-12.4 -51.3,-12.4 -52.7,-11.7 -52,-11.7 -51.3,-11.7 -54.7,13.7 -54,13.7 -53.3,13.7 -54.7,14.4 -54,14.4 -53.3,14.4 -54.7,15.1 -54,15.1 -53.3,15.1
  other v3: -32,-47.8 -31,-47.8 -30,-47.8 -29,-47.8 -28,-47.8 -29,-46.8 -28,-46.8
3V3_USB: C140.2 L22.2 R247.2 R248.2 R250.2 R257.2 R259.1 U24.27 U26.D | length 3.3
  1-TOP w0.2: R248.2@108.8,-39.02 v1(108.8,-38.4) ; R247.2@110.2,-39.02 v1(110.2,-38.4) ; R250.2@118.2,-31.52 v1(118.2,-30.9) ; v1(120.5,-34) U24.27@121,-34
  1-TOP w0.3: L22.2@115.4,-31.15 v1(115.4,-30.2)
  other v1: 102.2,-38.2 102.9,-38.2 103.6,-38.2 102.2,-37.5 102.9,-37.5 103.6,-37.5 102.2,-36.8 102.9,-36.8 103.6,-36.8
5V: C56.1 C82.2 C83.2 J24.1 J52.3 L17.1 R19.2 R132.1 U11.3 U20.1 | length 40.4
  1-TOP w0.2: U20.1@67,-48.2 v1(67.5,-48.2) C82.2@68.14,-48.2 ; U20.1@67,-47 v1(67.5,-47) C83.2@68.14,-47
  1-TOP w0.3: C56.1@0.5,48.9 C56.1@0.6,48.9 ; U11.3@0.6,50.53 C56.1@0.6,48.9 ; v1(1.1,48.9) C56.1@0.6,48.9
  1-TOP w0.4: R132.1@-13.4,57 v1(-12.6,57)
  1-TOP w0.5: L17.1@20.2,-54.15 v3(20.2,-53.1)
  1-TOP w0.7: R19.2@71,-46.2 v3(71,-45.3) v3(71,-44.5)
  8-BOTTOM w1: v3(78,-32) v3(78,-31) 78,-26.5 90,-14.5 95.31,-14.5 J52.3@98.54,-11.27
5V_DBG: C30.2 C37.2 C38.2 C39.2 R132.2 R135.2 R149.1 U8.1 U8.3 U9.3 U9.4 U9.42 | length 33.7
  1-TOP w0.2: U8.3@-25.32,58.95 -24.45,58.95 -24.3,58.8 -24.3,57.05 ; U9.4@-20.75,51.63 U9.4@-20.75,51.67 -20.75,52.55 -20.6,52.7 -20.25,52.7 ; U9.3@-20.25,51.63 U9.3@-20.25,51.67 -20.25,52.7 ; C38.2@-18,52.7 -20.25,52.7 ; U9.42@-17.83,47.25 v1(-16.7,47.25) C39.2@-15.9,47.25 ; R149.1@-16.2,50.985 v1(-16.2,51.9)
  1-TOP w0.4: U8.1@-25.32,57.05 -24.3,57.05 v1(-23,57.05) ; C38.2@-18,52.54 C37.2@-16.2,52.54 ; v1(-16.2,51.9) C37.2@-16.2,52.54 ; R132.2@-15,57 -15,53.2 -15.66,52.54 C37.2@-16.2,52.54
  3-INTOP w0.4: v1(-23,57.05) -15.85,57.05 v1(-15,56.2)
  6-INBOT w0.4: v1(-16.7,47.25) -16.7,51.4 v1(-16.2,51.9)
5V_DVK_PWR_ON: R25.1 U3.4 U5.E26 | length 140
  1-TOP w0.2: U5.E26@-15.24,13.97 v1(-14.605,14.605) ; v1(69.5,-32) 77.25,-39.75 U3.4@77.25,-46.19
  3-INTOP w0.15: v1(-3.1,-26) -1.6,-24.5 45.2,-24.5 49.7,-29 52.7,-32 v1(69.5,-32)
  6-INBOT w0.15: v1(-14.605,14.605) -13.97,13.97 -13.97,12.97 -12.54,11.54 -12.54,-0.06 -11.59,-1.01 -11.59,-17.51 v1(-3.1,-26)
5V_OUT_HDMI: C101.2 J31.18 R233.1 R234.1 U20.38 | length 4.1
  1-TOP w0.2: v1(55.3,-51.8) R234.1@55.92,-51.8 ; v1(55.3,-50.7) R233.1@55.92,-50.7 ; J31.18@57,-56.5 v1(57,-54.8) ; U20.38@67,-53.4 v1(67.5,-53.4) C101.2@68.14,-53.4
ADDR: R245.1 R246.2 U21.64 | length 3.2
  1-TOP w0.2: R245.1@-10.52,-51.6 R246.2@-10.52,-50.4 ; R246.2@-10.5,-50.3 -10.1,-50.3 -9.55,-49.75 U21.64@-8.68,-49.75
AUD_I2C_SCL: R296.2 U29.51 | length 137.2
  1-TOP w0.15: v1(-59.1,34.3) -59,34.4 U29.51@-57.43,34.4
  1-TOP w0.2: v1(67.9,23) R296.2@68.5,23
  3-INTOP w0.15: v1(-59.1,34.3) -56.8,32 -47.393,32 -45.393,30 48.1,30 50.1,28 67.567,28 68.5,27.067 68.5,23.6 v1(67.9,23)
AUD_I2C_SDA: R298.2 U29.52 | length 132.2
  1-TOP w0.15: v1(-59.1,33.6) -58.7,34 U29.52@-57.43,34
  1-TOP w0.2: v1(67.9,26.96) R298.2@68.5,26.96
  3-INTOP w0.15: v1(-59.1,33.6) -57,31.5 -47.6,31.5 -45.6,29.5 47.9,29.5 49.9,27.5 67.36,27.5 v1(67.9,26.96)
AUD_INT#: R268.2 U5.AG8 U29.56 | length 124.4
  1-TOP w0.15: R268.2@-60.52,29.8 v1(-59.9,29.8) -57.7,32 U29.56@-57.7,32.4
  1-TOP w0.2: U5.AG8@12.7,-8.89 v1(13.335,-9.525)
  3-INTOP w0.15: v1(-59.9,29.8) -59.2,29.1 -46.6,29.1 -45,27.5 -45,23.093 -33.472,11.565 -22.635,11.565 -22.34,11.27 -13.07,11.27 -12.7,10.9 -12.7,-17.2 -12.28,-17.62 12.262,-17.62 12.7,-17.182 12.7,-10.16 v1(13.335,-9.525)
AUD_PWR_EN: Q7.G Q9.G R281.2 R285.2 U5.E27 | length 51.8
  1-TOP w0.2: R281.2@-56.5,13.1 -56.5,11 ; Q7.G@-55.81,11 -56.5,11 ; R285.2@-51,13.1 -51,9.55 ; v1(-37,16.5) -43.95,9.55 Q9.G@-49.85,9.55 -51,9.55 ; v1(-15.875,15.875) U5.E27@-15.24,15.24 ; -56.5,11 -56.5,10.579 -55.471,9.55 -51,9.55
  3-INTOP w0.15: v1(-37,16.5) -16.5,16.5 v1(-15.875,15.875)
BOOT_TOGLE: R117.2 S1.3 U7.19 | length 37.2
  1-TOP w0.2: U7.19@103.275,17.1 103.275,16.225 103.98,15.52 R117.2@105,15.52 105.52,15.52 107.5,17.5 107.5,22.7 118.53,33.73 S1.3@128.7,33.73
BT_GPIO_2: J44.2 U5.E10 | length 55.5
  1-TOP w0.2: J44.2@-65.73,2.92 -61.077,2.92 -58.157,0 -55.5,0 v1(-50,-5.5) ; v1(-15.875,-6.985) U5.E10@-15.24,-6.35
  3-INTOP w0.15: v1(-50,-5.5) -23.75,-5.5 -21.49,-7.76 -18.094,-7.76 -17.954,-7.62 -16.51,-7.62 v1(-15.875,-6.985)
BT_GPIO_3: J44.4 U5.E11 | length 55.6
  1-TOP w0.2: J44.4@-65.73,5.46 -62.203,5.46 -57.743,1 -55.5,1 v1(-51,-3.5) ; v1(-15.875,-5.715) U5.E11@-15.24,-5.08
  3-INTOP w0.15: v1(-51,-3.5) -22.921,-3.5 -20.921,-5.5 -20.3,-5.5 -20.04,-5.24 -16.35,-5.24 v1(-15.875,-5.715)
BT_GPIO_5: J44.6 U5.G15 | length 56.8
  1-TOP w0.2: J44.6@-65.73,8 -63.328,8 v1(-57.828,2.5) ; v1(-13.335,0.635) U5.G15@-12.7,0
  3-INTOP w0.15: v1(-57.828,2.5) -20.7,2.5 -20.3,2.5 -20.18,2.38 -14.28,2.38 -13.97,2.07 -13.97,1.27 v1(-13.335,0.635)
BT_UART1_CTS#: J49.9 R58.2 | length 6.6
  1-TOP w0.2: J49.9@-65.73,-14.27 -62.46,-11 R58.2@-60.48,-11
BT_UART1_RTS#: J49.7 R59.2 | length 6.4
  1-TOP w0.2: J49.7@-65.73,-16.81 -62.92,-14 R59.2@-60.48,-14
BT_UART1_RX: J49.5 R57.2 | length 6.2
  1-TOP w0.2: J49.5@-65.73,-19.35 -63.38,-17 R57.2@-60.48,-17
BT_UART1_TX: J49.3 R56.2 | length 6
  1-TOP w0.2: J49.3@-65.73,-21.89 -63.84,-20 R56.2@-60.48,-20
BT_WAKEUP_HOST: J44.1 U5.G17 | length 57.4
  1-TOP w0.2: J44.1@-68.27,2.92 -66.85,1.5 v1(-60.5,1.5) ; v1(-13.335,3.175) U5.G17@-12.7,2.54
  3-INTOP w0.15: v1(-60.5,1.5) -59,3 -20.2,3 -19.9,2.7 -13.81,2.7 v1(-13.335,3.175)
BT_WAKEUP_SLAVE: J44.3 U5.G12 | length 60.3
  1-TOP w0.2: J44.3@-68.27,5.46 -67,4.19 -61.64,4.19 v1(-57.95,0.5) ; v1(-13.335,-4.445) U5.G12@-12.7,-3.81
  3-INTOP w0.15: v1(-57.95,0.5) -21.3,0.5 -20.64,-0.16 -17.022,-0.16 -14.682,-2.5 -14.608,-2.5 -14.13,-2.978 -14.13,-3.65 v1(-13.335,-4.445)
CAN1_H: D18.2 J23.1 J24.2 U11.7 | length 8.3
  1-TOP w0.2: J24.2@-1.27,63.5 -1.27,63.311 -0.645,62.686 U11.7@-0.645,55.47
CAN1_L: D17.2 J24.3 R166.1 U11.6 | length 8.3
  1-TOP w0.2: U11.6@0.625,55.47 0.625,62.706 1.27,63.351 J24.3@1.27,63.5
CAN_MODE: R167.1 U5.E18 | length 62
  1-TOP w0.2: v1(-15.875,4.445) U5.E18@-15.24,3.81 ; R167.1@-4.48,54 -4.48,42.98 -2.5,41 -2.5,36.5 v1(0,34)
  6-INBOT w0.15: v1(-15.875,4.445) -15.24,5.08 -15.24,9.64 -15.76,10.16 -17.26,10.16 -17.64,10.54 -17.64,13.56 -17.2,14 -17,14 -16.51,14.49 -16.51,15.912 -14.642,17.78 -14.42,17.78 -13.97,18.23 -13.97,19.63 0,33.6 v1(0,34)
CAN_NINT: U5.AA1 U10.4 | length 75.9
  1-TOP w0.2: U10.4@4.53,48 v1(6,48) ; U5.AA1@5.08,-17.78 v1(5.715,-18.415)
  6-INBOT w0.15: v1(5.715,-18.415) 9.885,-18.415 11.5,-16.8 11.5,42.5 v1(6,48)
CAN_NINT0: U5.AN4 U10.9 | length 69.4
  1-TOP w0.2: U10.9@9.47,45.46 14.22,45.46 20,39.68 v1(20,37) ; U5.AN4@20.32,-13.97 v1(20.955,-14.605)
  6-INBOT w0.15: v1(20,37) 20,11.9 22,9.9 22,-13.56 v1(20.955,-14.605)
CAN_NINT1: U5.AN5 U10.8 | length 66.7
  1-TOP w0.2: U10.8@9.47,44.19 14.69,44.19 19.5,39.38 v1(19.5,36.5) ; U5.AN5@20.32,-12.7 v1(20.955,-13.335)
  6-INBOT w0.15: v1(19.5,36.5) 19.5,11.7 21.5,9.7 21.5,-12.79 v1(20.955,-13.335)
CAN_RX: U10.2 U11.4 | length 2.6
  1-TOP w0.2: U11.4@1.905,50.54 U10.2@4.53,50.54
CAN_TX: U10.1 U11.1 | length 7.7
  1-TOP w0.2: U11.1@-1.915,50.53 -1.915,51.685 -1.79,51.81 U10.1@4.53,51.81
CLKIN1: J50.1 U5.AM10 | length 99.1
  1-TOP w0.2: U5.AM10@19.05,-6.35 v1(19.685,-6.985)
  3-INTOP w0.15: v1(19.685,-6.985) 21.815,-6.985 22.8,-6 v1(102.5,-6)
  6-INBOT w0.15: v1(102.5,-6) 102.5,-17.61 J50.1@104.89,-20
CLKIN2: J50.3 U5.AM11 | length 96.7
  1-TOP w0.2: U5.AM11@19.05,-5.08 v1(19.685,-5.715)
  3-INTOP w0.15: v1(19.685,-5.715) 20.16,-6.19 21.21,-6.19 22.4,-5 v1(99.8,-5)
  6-INBOT w0.15: v1(99.8,-5) 99.8,-19.99 J50.3@99.81,-20
CLKOUT1: J50.5 U5.AM7 | length 82.1
  1-TOP w0.2: U5.AM7@19.05,-10.16 v1(19.685,-10.795)
  3-INTOP w0.15: v1(19.685,-10.795) 20.59,-11.7 55.049,-11.7 55.849,-12.5 87.23,-12.5 89.23,-14.5 93.3,-14.5 94.73,-15.93 J50.5@94.73,-20
CLKOUT2: J50.7 U5.AM9 | length 81.7
  1-TOP w0.2: U5.AM9@19.05,-7.62 v1(19.685,-8.255)
  3-INTOP w0.15: v1(19.685,-8.255) 21.945,-8.255 23.2,-7 50.7,-7 52.7,-9 v1(87,-9)
  6-INBOT w0.15: v1(87,-9) 87,-17.35 J50.7@89.65,-20
CONSOLE_RX: J17.3 R141.2 U5.V29 | length 65.6
  1-TOP w0.2: J17.3@-32,54.73 -33.2,53.53 -33.2,47.6 v1(-30.6,45) R141.2@-29.8,45 ; v1(-3,33) -3,27.2 1.27,22.93 U5.V29@1.27,17.78
  3-INTOP w0.15: v1(-30.6,45) -8.3,45 -5,41.7 -5,35 v1(-3,33)
CONSOLE_TX: J17.2 R142.2 U5.W29 | length 62.3
  1-TOP w0.2: J17.2@-32,52.19 -30.6,50.79 v1(-30.6,46.5) R142.2@-29.8,46.5 ; v1(-2.5,33.5) -2.5,27.5 1.8,23.2 1.8,18.52 U5.W29@2.54,17.78
  3-INTOP w0.15: v1@-30.7,46.5 v1(-30.6,46.5) -9,46.5 -4.5,42 -4.5,35.5 v1(-2.5,33.5)
CT: C65.2 C182.2 C183.2 C184.2 J27.1
DVDDL1: C68.2 C69.2 L5.2 L7.2 R185.1 U15.47 | length 5.2
  1-TOP w0.15: U15.47@-54.8,-29.95 v1(-54.8,-29.1)
  1-TOP w0.2: R185.1@-52.4,-24.52 v1(-52.4,-23.9)
  1-TOP w0.3: v1(-54.8,-29.1) C69.2@-54.8,-28.46 ; L7.2@-53.7,-24.52 v1(-53.7,-23.875)
  1-TOP w0.4: v1(-60.4,-26.4) C68.2@-60.4,-27.04 L5.2@-58.6,-27.04
ENET_PWR: Q2.G R174.2 U5.AF1 | length 67.9
  1-TOP w0.2: Q2.G@-50.19,-9 -49.5,-9 ; R174.2@-49.5,-11.1 -49.5,-9 ; v1(-47.5,-9.5) -48,-9 -49.5,-9 ; v1(10.795,-18.415) U5.AF1@11.43,-17.78
  3-INTOP w0.15: v1(-47.5,-9.5) -26.8,-9.5 -21.06,-15.24 -15.24,-15.24 -12.54,-17.94 -12,-17.94 10.32,-17.94 v1(10.795,-18.415)
ETH1_TXRXA_N: J27.3 U15.12 | length 18.1
  1-TOP w0.15: U15.12@-55.95,-35.2 -55.973,-35.177 -56.595,-35.177 -57.2,-35.782 -57.2,-41.699 -54.779,-44.12 -54.779,-45.4 -54.779,-45.775 -54.779,-46.055 -54.709,-46.125 -54.301,-46.125 -54.231,-46.195 -54.231,-46.405 -54.301,-46.475 -54.709,-46.475 -54.779,-46.545 -54.779,-46.825 -54.779,-47 -54.779,-48.962 -54.691,-49.05 -54.567,-49.05 J27.3@-53.675,-48.158
ETH1_TXRXA_P: J27.2 U15.11 | length 18.2
  1-TOP w0.15: U15.11@-55.95,-34.8 -55.973,-34.823 -56.742,-34.823 -57.554,-35.635 -57.554,-41.846 -55.133,-44.267 -55.133,-49.109 -54.856,-49.386 -54.856,-50.609 J27.2@-54.945,-50.698
ETH1_TXRXB_N: J27.5 U15.15 | length 18.1
  1-TOP w0.15: U15.15@-54.4,-35.95 -54.423,-35.973 -54.423,-36.742 -55.035,-37.353 -55.253,-37.353 -55.7,-37.8 -55.7,-41.6 -54.8,-42.5 -53.299,-42.5 -51.9,-43.899 -51.9,-45 -52.239,-45.339 -52.239,-45.4 -52.239,-46.055 -52.169,-46.125 -52.054,-46.125 -51.984,-46.195 -51.984,-46.405 -52.054,-46.475 -52.169,-46.475 -52.239,-46.545 -52.239,-46.825 -52.239,-47 -52.239,-48.962 -52.151,-49.05 -52.027,-49.05 J27.5@-51.135,-48.158
ETH1_TXRXB_P: J27.4 U15.14 | length 18.2
  1-TOP w0.15: U15.14@-54.8,-35.95 -54.777,-35.973 -54.777,-36.595 -55.181,-36.999 -55.4,-36.999 -56.054,-37.653 -56.054,-41.747 -54.947,-42.854 -53.446,-42.854 -52.254,-44.046 -52.254,-44.853 -52.593,-45.192 -52.593,-49.109 -52.316,-49.386 -52.316,-50.609 J27.4@-52.405,-50.698
ETH1_TXRXC_N: J27.7 U15.18 | length 18.1
  1-TOP w0.15: U15.18@-53.2,-35.95 -53.223,-35.973 -53.223,-40.377 -52.2,-41.4 -50.8,-41.4 -48.546,-43.654 -48.546,-44.474 -49.699,-45.628 -49.699,-46.055 -49.629,-46.125 -49.514,-46.125 -49.444,-46.195 -49.444,-46.405 -49.514,-46.475 -49.629,-46.475 -49.699,-46.545 -49.699,-46.825 -49.699,-47 -49.699,-48.962 -49.611,-49.05 -49.487,-49.05 J27.7@-48.595,-48.158
ETH1_TXRXC_P: J27.6 U15.17 | length 18.1
  1-TOP w0.15: U15.17@-53.6,-35.95 -53.577,-35.973 -53.577,-40.524 -52.347,-41.754 -50.947,-41.754 -48.9,-43.801 -48.9,-44.328 -50.053,-45.481 -50.053,-49.109 -49.776,-49.386 -49.776,-50.609 J27.6@-49.865,-50.698
ETH1_TXRXD_N: J27.9 U15.21 | length 18.1
  1-TOP w0.15: U15.21@-52,-35.95 -52.023,-35.973 -52.023,-36.293 -52.023,-36.505 -51.246,-37.282 -51.246,-39.953 -50.999,-40.2 -48.9,-40.2 -47.159,-41.941 -47.159,-45.6 -47.159,-46.055 -47.089,-46.125 -46.974,-46.125 -46.904,-46.195 -46.904,-46.405 -46.974,-46.475 -47.089,-46.475 -47.159,-46.545 -47.159,-46.825 -47.159,-47 -47.159,-48.962 -47.071,-49.05 -46.947,-49.05 J27.9@-46.055,-48.158
ETH1_TXRXD_P: J27.8 U15.20 | length 18.2
  1-TOP w0.15: U15.20@-52.4,-35.95 -52.377,-35.973 -52.377,-36.293 -52.377,-36.651 -51.6,-37.428 -51.6,-40.1 -51.146,-40.554 -49.047,-40.554 -47.513,-42.088 -47.513,-49.109 -47.236,-49.386 -47.236,-50.609 J27.8@-47.325,-50.698
EXP_I2C_GPIO: J48.7 U5.AG26 | length 121.4
  1-TOP w0.2: U5.AG26@12.7,13.97 v1(13.335,14.605)
  3-INTOP w0.15: v1(13.335,14.605) 13.97,15.24 14.74,15.24 15.24,15.74 15.24,15.94 15.81,16.51 17.11,16.51 20.6,20 61.5,20 62,19.5 v1(70.5,19.5)
  6-INBOT w0.15: v1(70.5,19.5) 70.5,3.1 84,-10.4 84,-20.9 90.25,-27.15 90.6,-27.5 91.5,-27.5 92.19,-28.19 92.19,-30 J48.7@93.46,-31.27
EXP_I2C_IRQ_N: J48.5 U5.AG27 | length 124
  1-TOP w0.2: U5.AG27@12.7,15.24 v1(13.335,15.875)
  3-INTOP w0.15: v1(13.335,15.875) 13.97,16.51 14.71,16.51 15.24,17.04 15.24,17.24 15.78,17.78 17.68,17.78 20.4,20.5 61.7,20.5 62.2,20 v1(71,20)
  6-INBOT w0.15: v1(71,20) 71,3.3 84.5,-10.2 84.5,-20.693 90.813,-27.006 93.506,-27.006 94.73,-28.23 94.73,-30 J48.5@96,-31.27
EXP_I2C_SCL: J48.1 U5.V1 | length 110
  1-TOP w0.2: U5.V1@1.27,-17.78 v1(5.49,-22)
  3-INTOP w0.15: v1(5.49,-22) 7.6,-22 8.1,-21.5 8.7,-21.5 9.7,-22.5 66.115,-22.5 70.115,-26.5 85.5,-26.5 88,-24 97.5,-24 99.81,-26.31 99.81,-30 J48.1@101.08,-31.27
EXP_I2C_SDA: J48.3 U5.W1 | length 104.7
  1-TOP w0.2: U5.W1@2.54,-17.78 6.76,-22 v1(8.5,-22)
  3-INTOP w0.15: v1(8.5,-22) 9.506,-23.006 65.905,-23.006 69.906,-27.006 85.7,-27.006 88.206,-24.5 93.6,-24.5 97.27,-28.17 97.27,-30 J48.3@98.54,-31.27
FAA_N: L26.1 U24.8 | length 29.6
  1-TOP w0.168: v1(119.2,-17.425) 119.29,-17.425 119.456,-17.259 119.791,-17.259 120.159,-16.891 120.159,-16.314 120.257,-16.216 120.284,-16.216 120.4,-16.1 L26.1@120.4,-15.85 ; v1(124.425,-40.7) 124.462,-40.662 124.462,-39.837 U24.8@124.5,-39.8
  8-BOTTOM w0.168: v1(119.2,-17.425) 119.29,-17.425 119.456,-17.259 119.659,-17.259 124.9,-22.5 124.9,-32.15 124.591,-32.459 124.591,-40.444 124.425,-40.61 v1(124.425,-40.7)
FAA_P: L26.4 U24.9 | length 29.6
  1-TOP w0.168: v1(119.2,-16.775) 119.29,-16.775 119.456,-16.941 119.659,-16.941 119.841,-16.759 119.841,-16.314 119.743,-16.216 119.716,-16.216 119.6,-16.1 L26.4@119.6,-15.85 ; U24.9@125,-39.8 125.037,-39.837 125.037,-40.662 v1(125.075,-40.7)
  8-BOTTOM w0.168: v1(119.2,-16.775) 119.29,-16.775 119.456,-16.941 119.791,-16.941 125.218,-22.368 125.218,-32.282 124.909,-32.591 124.909,-40.444 125.075,-40.61 v1(125.075,-40.7)
FT230_USB_N: R138.2 U9.8 | length 6.7
  1-TOP w0.15: U9.8@-22.75,51.67 -22.75,50.75 v1(-22.5,50.5) ; v1(-19.675,53.4) -19.675,53.845 R138.2@-19.5,54.02
  8-BOTTOM w0.168: v1(-22.5,50.5) -22.5,51.291 -22.3,51.491 -21.209,51.491 -19.841,52.859 -19.841,53.144 -19.675,53.31 v1(-19.675,53.4)
FT230_USB_P: R139.2 R145.1 U9.7 | length 6.8
  1-TOP w0.15: v1(-22.5,52.8) -22.25,52.55 U9.7@-22.25,51.67 ; R139.2@-20.5,54.02 -20.325,53.845 v1(-20.325,53.4)
  1-TOP w0.2: v1(-22.5,52.8) R145.1@-22.5,53.52
  8-BOTTOM w0.168: v1(-22.5,52.8) -22.5,52.009 -22.3,51.809 -21.341,51.809 -20.159,52.991 -20.159,53.144 -20.325,53.31 v1(-20.325,53.4)
FTDI_3V3_OUT: C36.1 R134.1 U9.6 | length 9.3
  1-TOP w0.2: R134.1@-26.5,53.5 -25.3,53.5 -25.3,50.8 -24.5,50 -22,50 -21.75,50.25 U9.6@-21.75,51.67
G_N: L25.4 U24.6 | length 32.5
  1-TOP w0.168: L25.4@113.6,-14.85 113.637,-14.888 113.637,-15.663 v1(113.675,-15.7) ; v1(123.425,-41.4) 123.425,-41.31 123.591,-41.144 123.591,-40.696 123.591,-40.364 123.566,-40.339 123.566,-39.866 U24.6@123.5,-39.8
  8-BOTTOM w0.168: v1(113.675,-15.7) 113.675,-15.79 113.841,-15.956 113.841,-16.691 120.482,-23.332 120.482,-31.732 122.882,-34.132 122.882,-39.082 123.591,-39.791 123.591,-41.144 123.425,-41.31 v1(123.425,-41.4)
G_P: L25.1 U24.7 | length 32.5
  1-TOP w0.168: v1(114.325,-15.7) 114.362,-15.663 114.362,-14.888 L25.1@114.4,-14.85 ; U24.7@124,-39.8 123.934,-39.866 123.934,-40.339 123.909,-40.364 123.909,-40.828 123.909,-41.144 124.075,-41.31 v1(124.075,-41.4)
  8-BOTTOM w0.168: v1(114.325,-15.7) 114.325,-15.79 114.159,-15.956 114.159,-16.559 120.8,-23.2 120.8,-31.6 123.2,-34 123.2,-38.95 123.909,-39.659 123.909,-41.144 124.075,-41.31 v1(124.075,-41.4)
